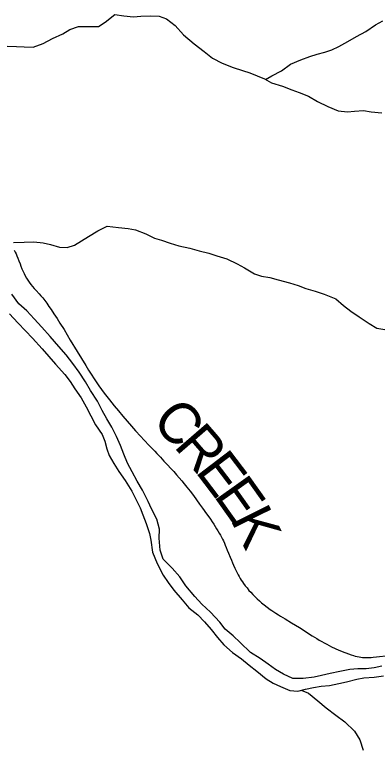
# Model space of a CAD drawing. Extents: x 1442749 to 1756758, y 235267 to 677782.
# Drawn here: x 1557967 to 1560618, y 512566 to 517900 of the extents above; entities that cross this region are included whole.
import ezdxf

# ---------------------------------------------------------------- set-up
doc = ezdxf.new("R2010")
doc.units = 0
for name, color, linetype in [('GM_X_Major_River', 7, 'Continuous'), ('GM_X_Minor_River', 7, 'Continuous'), ('GM_X_Township_Road', 7, 'Continuous'), ('GM_X_Township_Road_Text', 7, 'Continuous')]:
    doc.layers.add(name, color=color, linetype=linetype)

msp = doc.modelspace()

# ---------------------------------------------------------------- linework, layer by layer
at = {"layer": 'GM_X_Major_River'}
for points in [[(1558289.5, 515478.4), (1558227.6, 515550.2), (1558165.5, 515618), (1558109.3, 515679.7), (1558056.9, 515737.2), (1557998.4, 515788.9), (1557946.5, 515860.5)], [(1557930.3, 515716.7), (1557990.5, 515650.9), (1558046.8, 515591.3), (1558099.2, 515537.8), (1558169.1, 515461.7), (1558217.4, 515404.3), (1558265.8, 515348.9), (1558333.7, 515272.9), (1558372.2, 515221.7), (1558406.7, 515168.7), (1558454.8, 515103.3), (1558490.9, 515038.2), (1558525, 514971.1), (1558557.2, 514906.1), (1558607.2, 514836.6), (1558625.7, 514786), (1558642.2, 514731.5), (1558658.7, 514681), (1558691.1, 514624), (1558729.4, 514564.8)], [(1560650.8, 513143.7), (1560594.4, 513131.2), (1560536.2, 513124.8), (1560476.2, 513124.5), (1560416.1, 513120.1), (1560343.7, 513106.1), (1560273.2, 513090), (1560210.8, 513075.7), (1560156.5, 513065.2), (1560076.2, 513053.4), (1560000.2, 513055.5), (1559931.1, 513087.4), (1559874.1, 513121), (1559819.2, 513158.6), (1559762.4, 513200.2), (1559691.6, 513244.3), (1559615.7, 513318.5), (1559563.1, 513366), (1559506.5, 513415.6), (1559468, 513466.8), (1559398, 513538.8), (1559335.7, 513596.6), (1559285.3, 513652.1), (1559219.5, 513730), (1559175.4, 513797.4), (1559119.3, 513861), (1559053.1, 513924.9), (1559031, 513991.6), (1559023.5, 514078), (1559025.4, 514144), (1559007.4, 514216.6), (1558967.6, 514291.9), (1558943.2, 514346.6), (1558901.5, 514429.9), (1558863.4, 514495), (1558825.3, 514562.2), (1558791.2, 514627.2), (1558765, 514692.1), (1558740.8, 514754.8), (1558710.7, 514819.8), (1558676.7, 514888.8), (1558640.4, 514949.9), (1558606.2, 515011), (1558572.1, 515078), (1558522.4, 515157.5), (1558486.2, 515220.6), (1558438.1, 515290), (1558392, 515353.4), (1558343.8, 515416.8), (1558289.5, 515478.4)], [(1558729.4, 514564.8), (1558775.5, 514499.5), (1558823.3, 514422), (1558855.5, 514359), (1558883.8, 514300.2), (1558904.4, 514249.5), (1558928.6, 514186.8), (1558952.5, 514114), (1558963.1, 514063.6), (1558974.6, 513977.2), (1559008.2, 513894.1), (1559053.8, 513808.7), (1559088.2, 513755.7), (1559130.6, 513698.4), (1559190.6, 513628.7), (1559241, 513571.2), (1559305.5, 513519.3), (1559356, 513467.9), (1559404.4, 513412.4), (1559450.7, 513353.1), (1559495.2, 513299.8), (1559559.6, 513243.9), (1559626.3, 513198), (1559681, 513152.4), (1559737.7, 513108.8), (1559806.1, 513052.8), (1559857.2, 513021.3), (1559910.5, 512995.8), (1559977.7, 512968), (1560037.6, 512962.3), (1560092, 512976.8), (1560152.3, 512989.2), (1560206.6, 512997.7), (1560268.8, 513004), (1560337.2, 513018.1), (1560391.5, 513030.6), (1560468.1, 513048.6), (1560518.4, 513059.2), (1560594.5, 513065.1), (1560662.8, 513075.2)]]:
    msp.add_lwpolyline(points, dxfattribs=at)
at = {"layer": 'GM_X_Minor_River'}
for points in [[(1557912, 517669.2), (1557982, 517667.8), (1558037.9, 517664.7), (1558101.9, 517663.4), (1558176.5, 517690), (1558245.2, 517724.7), (1558319.9, 517759.3), (1558370.5, 517790.3), (1558435, 517813.1), (1558513, 517813.6), (1558579.1, 517814.3), (1558629.7, 517845.3), (1558700.8, 517900), (1558766.6, 517890.7), (1558836.5, 517883.3), (1558890.6, 517888.3), (1558960.7, 517890.9), (1559022.6, 517887.7), (1559076.2, 517868.6), (1559139.3, 517821.3), (1559201.9, 517751.9), (1559278.5, 517686.3), (1559351.4, 517630.8), (1559414.4, 517581.5), (1559483.7, 517546), (1559565.1, 517514.4), (1559632.6, 517493), (1559686.3, 517475.9), (1559739.8, 517452.9), (1559793.4, 517431.8), (1559844.8, 517402.7), (1559924.3, 517377.1), (1559993.8, 517351.7), (1560045.4, 517332.6), (1560114.8, 517305.2), (1560180.1, 517265.9), (1560255.3, 517230.3), (1560330.7, 517198.8), (1560398.6, 517191.5), (1560450.6, 517194.5), (1560516.7, 517199.2), (1560572.6, 517190), (1560650.4, 517182.5)], [(1559801.6, 517427.1), (1559845.8, 517452.8), (1559918.6, 517489.4), (1559983.6, 517538.2), (1560058.2, 517568.8), (1560124.8, 517593.5), (1560177.1, 517610.5), (1560233.4, 517625.4), (1560285.8, 517642.4), (1560336.3, 517667.5), (1560401.1, 517704.3), (1560465.8, 517739.1), (1560532.6, 517777.8), (1560603.6, 517826.5), (1560658.2, 517853.5)], [(1557958.6, 516235.9), (1558036.7, 516240.3), (1558106.8, 516241), (1558176.6, 516233.6), (1558228.4, 516222.5), (1558296, 516203.2), (1558352, 516200.1), (1558404.3, 516217.1), (1558457, 516248.1), (1558507.6, 516281.1), (1558576.5, 516321.8), (1558643.2, 516356.6), (1558727, 516346.9), (1558796.9, 516339.5), (1558850.7, 516328.5), (1558926.1, 516300.9), (1558989.5, 516269.6), (1559041.1, 516252.6), (1559104.7, 516231.3), (1559168.3, 516212), (1559248, 516194.4), (1559315.6, 516177.1), (1559387.3, 516159.6), (1559444.9, 516140.5), (1559518.4, 516117), (1559593.7, 516081.5), (1559647.1, 516052.3), (1559720.2, 516008.8), (1559771.9, 515991.8), (1559831.7, 515980.6), (1559893.3, 515963.4), (1559976.9, 515941.7), (1560038.5, 515922.4), (1560096.1, 515901.3), (1560163.7, 515881.9), (1560229.3, 515860.6), (1560314.5, 515824.8), (1560369.6, 515777.7), (1560424.7, 515734.5), (1560485.9, 515693.3), (1560558.9, 515645.8), (1560614.2, 515612.6), (1560686, 515599.2)], [(1560060, 512968.3), (1560115.5, 512948.1), (1560182.4, 512890.6), (1560243.3, 512839.4), (1560314.2, 512785.9), (1560381.3, 512738.5), (1560449.9, 512669), (1560490.6, 512608.1), (1560513, 512531.6)]]:
    msp.add_lwpolyline(points, dxfattribs=at)
at = {"layer": 'GM_X_Township_Road'}
msp.add_lwpolyline([(1557964.6, 516181.3), (1557972, 516167.4), (1557978.5, 516154.4), (1557984.6, 516140.1), (1557992, 516121.4), (1557998.5, 516103.2), (1558007.2, 516080.2), (1558013.7, 516063.2), (1558020.6, 516045.5), (1558028.9, 516025.9), (1558036.3, 516010.3), (1558044.9, 515993.8), (1558054.9, 515976.5), (1558064.4, 515961.2), (1558073.9, 515947), (1558086.2, 515930.9), (1558097.9, 515916.1), (1558110.9, 515901.4), (1558125.2, 515885.3), (1558145.6, 515862.3), (1558158.9, 515847.4), (1558172.5, 515831.9), (1558187.7, 515813.2), (1558202.9, 515792.9), (1558218.5, 515770.3), (1558233.7, 515748.1), (1558255, 515716), (1558277.6, 515681.3), (1558298.8, 515647.9), (1558328.3, 515600.6), (1558351.8, 515561.9), (1558374.3, 515524.6), (1558424.2, 515441.7), (1558488.1, 515338), (1558508, 515305.4), (1558525.8, 515276.4), (1558548, 515241.7), (1558567.3, 515212), (1558582.7, 515189.6), (1558601.8, 515163.5), (1558621.3, 515137.5), (1558640.4, 515112.7), (1558659.5, 515088.9), (1558695.1, 515044.6), (1558725.5, 515008.1), (1558758.7, 514968.5), (1558789.7, 514932.6), (1558820.4, 514897.4), (1558851.3, 514862.7), (1558887, 514823.8), (1558914.7, 514793.7), (1558951.6, 514754.6), (1558974.6, 514730.8), (1558991.5, 514713.9), (1559007.6, 514696.9), (1559032.3, 514669.6), (1559058.4, 514640.9), (1559083.6, 514614), (1559109.2, 514586.7), (1559129.6, 514565), (1559150.4, 514542), (1559169.1, 514519.8), (1559188.2, 514497.3), (1559205.9, 514476), (1559225.5, 514452.2), (1559249.3, 514422.2), (1559273.7, 514390.9), (1559297.1, 514358.8), (1559319.2, 514327.7), (1559340.5, 514297.6), (1559369.1, 514256.8), (1559385.3, 514234.5), (1559397.8, 514216.5), (1559410.8, 514197.4), (1559422.4, 514180.4), (1559432.5, 514164.8), (1559443.5, 514147.6), (1559452.5, 514132.7), (1559462.5, 514116.2), (1559470.7, 514101.9), (1559479.4, 514086.7), (1559486.7, 514072.4), (1559493.3, 514058.9), (1559500.2, 514043.3), (1559506.7, 514027.2), (1559513.7, 514010.3), (1559521.1, 513992.1), (1559530.1, 513969.9), (1559541.8, 513941.1), (1559551.4, 513918.3), (1559559.8, 513899.4), (1559567.4, 513882.2), (1559577.5, 513860.1), (1559587, 513839.7), (1559594, 513825.8), (1559600.9, 513812.4), (1559607.8, 513798.9), (1559616.1, 513784.6), (1559623.5, 513772.5), (1559631.3, 513760.8), (1559640.7, 513747.6), (1559652.1, 513732.1), (1559665.6, 513715.2), (1559679.9, 513697.8), (1559692.5, 513683.9), (1559706.8, 513668.7), (1559724.4, 513651.2), (1559739.8, 513636.6), (1559756, 513621.5), (1559771.5, 513608), (1559789.7, 513592.8), (1559813.2, 513574.5), (1559834, 513559.3), (1559847.4, 513549.8), (1559860.5, 513540.7), (1559876.5, 513530.3), (1559895.2, 513518.5), (1559910.5, 513509.2), (1559943.1, 513489.6), (1559989.4, 513461.7), (1560048, 513425.7), (1560141.3, 513367.1), (1560158.2, 513356.7), (1560176.3, 513345.4), (1560193.8, 513335), (1560212, 513324.1), (1560228.5, 513315), (1560247.6, 513304.9), (1560265.8, 513295.5), (1560283.6, 513286.8), (1560309.7, 513274.2), (1560335.3, 513262.5), (1560356.6, 513253.4), (1560372.8, 513246.9), (1560388.2, 513240.8), (1560407.8, 513233.4), (1560425.6, 513227.3), (1560442.8, 513221.5), (1560455.1, 513218.2), (1560471.1, 513214.3), (1560485.5, 513211.7), (1560498, 513209.8), (1560508.9, 513208.7), (1560521.2, 513207.7), (1560535.4, 513207.3), (1560550.1, 513207.3), (1560564, 513207.8), (1560573.6, 513208.2), (1560587.4, 513209.5), (1560612.7, 513212.5), (1560702.5, 513223)], dxfattribs=at)

# ---------------------------------------------------------------- texts
at = {"layer": 'GM_X_Township_Road_Text'}
for s, rotation, p in [('C', 311.9628, (1558960.9, 514930.2)), ('R', 310.8856, (1559124.7, 514748.1)), ('E', 307.3225, (1559282.9, 514565.6)), ('E', 305.4228, (1559417.4, 514389.3)), ('K', 296.3663, (1559541, 514217.2))]:
    msp.add_text(s, height=300, rotation=rotation, dxfattribs=at).set_placement(p)

doc.saveas('drawing.dxf')
